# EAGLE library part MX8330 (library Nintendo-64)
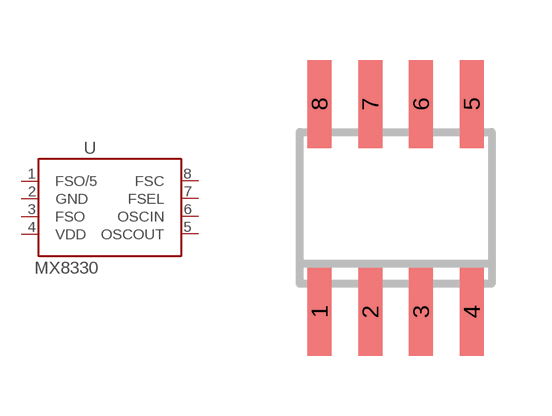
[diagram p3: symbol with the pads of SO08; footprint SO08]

Designator prefix -

## MX8330MC  [SO08]
1  FSO/5  out
2  GND  pwr
3  FSO  out
4  VDD  pwr
5  OSCOUT  out
6  OSCIN  in
7  FSEL  in
8  FSC  out

## Footprint SO08 (pad centres in mm)
smd 0.6 x 2.2: 1 -1.905,-2.6; 2 -0.635,-2.6; 3 0.635,-2.6; 4 1.905,-2.6; 5 1.905,2.6; 6 0.635,2.6; 7 -0.635,2.6; 8 -1.905,2.6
